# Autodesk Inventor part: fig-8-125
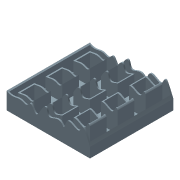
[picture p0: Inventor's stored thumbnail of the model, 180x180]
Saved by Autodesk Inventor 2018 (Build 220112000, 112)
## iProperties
Shininess: 64.0
Length Units: 11269
Angle Units: 11279
Time Units: 11290
Mass Units: 11283
Length Display Precision: 3
Angle Display Precision: 2
Compacted: True
Part Number: fig-8-125
Document SubType Name: Modeling
Created: 2002-12
Designer: deepak
Density: 1 g/cm^3
Material: Generic
Appearance: Light Steel Blue
Density: 0.0
Volumn: 0.0
Area: 0.0
PropertySet Name: Model Information
Control State: 0
Master: False
Checked Out: False
Author: deepak
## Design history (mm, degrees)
sketch "Sketch1"
  geometry: L1 (-32.188, 30.089)-(27.812, 30.089); L2 (27.812, 30.089)-(27.812, -29.911); L3 (27.812, -29.911)-(-32.188, -29.911); L4 (-32.188, -29.911)-(-32.188, 30.089)
  constraints: 8 end point, 2 parallel, 1 horizontal, 1 perpendicular
  dimensions: "d0" = 60 distance of L1.start L1.end; "d1" = 60 distance of L3.end L1.start
extrude "Extrusion1" new body sketch "Sketch1" stored distance "d2" = 20; taper "d3" = 0 deg
sketch "Sketch5"
  geometry: L1 (-27.812, 30.089)-(32.188, 30.089) reference; L2 (-27.812, -29.911)-(-27.812, 30.089) reference; L3 (-22.812, 25.089)-(-12.812, 25.089); L4 (-12.812, 25.089)-(-12.812, 15.089); L5 (-12.812, 15.089)-(-22.812, 15.089); L6 (-22.812, 15.089)-(-22.812, 25.089)
  constraints: 8 end point, 2 parallel, 1 horizontal, 1 perpendicular
  dimensions: "d8" = 10 distance of L3.start L3.end; "d9" = 10 distance of L5.end L3.start; "d10" = 5 distance between parallel lines of L2 L6; "d11" = 5 distance between parallel lines of L1 L3
extrude "Extrusion2" cut sketch "Sketch5" distance "d12" = 50; taper "d13" = 0 deg
pattern_linear "Rectangular Pattern1" dims "d16" = 20, "d19" = 20
shell "Shell2" dims "d21" = 1
sketch "Sketch2"
  geometry: 17 further points
  constraints: 17 other
extrude_surface "ExtrusionSrf1" sketch "Sketch2" dims "d4" = 70, "d5" = 0
split "Split2"
body "Solid1"
body "Srf1"
